Omron CX-Programmer project NewProject (CX-Programmer 9.81)

# PLC NewPLC1: CJ2M CPU11
I/O table (CPU CJ2M-CPU11): rack 0 slot 0 CJ1W-ETN21(ETN21Mode)

## Program NewProgram1 (cyclic task 0)
Local symbols
ETN_CloseRequest 1522.13 BOOL  ; Close Request Switch for ETN Unit
ETN_DataReceived 1516.13 BOOL  ; Data Received Judgment Bit for ETN Unit
ETN_LocalPortNo D30089 UINT  ; Local port number for ETN Unit
ETN_NumberOfSend_ReceiveDataBytes D30093 INT  ; Number of byes of send/receive data for ETN Unit
ETN_NumberOfTCPReceiveDataBytes D30008 UINT  ; Number of byes of TCP receive data for ETN Unit
ETN_OpenRequest 1522.10 BOOL  ; TCP Active Open Request Switch for ETN Unit
ETN_ReceiveRequest 1522.12 BOOL  ; Receive Request Switch for ETN Unit
ETN_RemoteIPAddress_1 D30090 UINT  ; Remote IP address for ETN Unit
ETN_RemoteIPAddress_2 D30091 UINT  ; Remote IP address for ETN Unit
ETN_RemotePortNo D30092 UINT  ; Remote port number for ETN Unit
ETN_ResponseCode D30097 UINT  ; Response code for ETN Unit
ETN_SendRequest 1522.11 BOOL  ; Send Request Switch for ETN Unit
ETN_Send_ReceiveDataAddress_1 D30094 UINT  ; Send/receive data address for ETN Unit
ETN_Send_ReceiveDataAddress_2 D30095 UINT  ; Send/receive data address for ETN Unit
ETN_SocketNo8 D30088 UINT  ; Socket option for ETN Unit/Socket No. 8
ETN_TCPConnectionStatus D30016 UINT  ; TCP connection status for ETN Unit
ETN_TimeoutValue D30096 UINT  ; Timeout value for ETN Unit
Input_CloseMonitorTime_BCD 5013 UINT_BCD  ; Close monitoring time (BCD)
Input_NumberOfSendDataBytes D9000 UINT  ; Number of bytes of send data
Input_OpenMonitorTime_BCD 5010 UINT_BCD  ; Open monitoring time (BCD)
Input_ReceiveMonitorTime_BCD 5012 UINT_BCD  ; Receive monitoring time (BCD)
Input_ReceiveProcessingRequired_NotRequired 5020 UINT  ; Sets whether or not receive processing is required for send processing.
Input_ReceiveStandbyTime_BIN 5014 UINT  ; Receive Standby Time (BIN)
Input_SendData D9001 WORD[128]  ; Send data
Input_SendMonitorTime_BCD 5011 UINT_BCD  ; Send monitoring time (BCD)
Input_Start 5000.00 BOOL  ; Switch to start communications processing (Manually turned ON)
Internal_CloseErrorEnd 5004.02 BOOL  ; Error end ЃЁ End of communications
Internal_CloseExecuting 5004.00 BOOL  ; Keeps ON status until end of close processing.
Internal_CloseMonitorTimerON T1003 BOOL  ; Close processing monitor timer
Internal_CloseNormalEnd 5004.01 BOOL  ; Normal end ЃЁ End of communications
Internal_CloseResponseCodeError 5004.03 BOOL  ; ResponseCodeError
Internal_CloseStatusError 5004.05 BOOL  ; TCP close status error
Internal_CloseTimeout 5004.04 BOOL  ; Timeout
Internal_CommunicationsExecuting 5000.01 BOOL  ; Keeps ON status until end of communications processing. ЃЁ To open processing
Internal_InitialSetupEnd 5000.04 BOOL  ; Ends initial setup. ЃЁ To open processing
Internal_OpenErrorEnd 5001.02 BOOL  ; Error end ЃЁ Close processing
Internal_OpenExecuting 5001.00 BOOL  ; Keeps ON status until end of open processing.
Internal_OpenMonitorTimerON T1000 BOOL  ; Open processing monitor timer
Internal_OpenNormalEnd 5001.01 BOOL  ; Normal end ЃЁ To send processing
Internal_OpenResponseCodeError 5001.03 BOOL  ; ResponseCodeError
Internal_OpenTimeout 5001.04 BOOL  ; Timeout
Internal_ReceiveCodeReaderError 5003.05 BOOL  ; Code reader error
Internal_ReceiveDataAddressType 5110 UINT  ; Receive data address type
Internal_ReceiveDataFirstWord 5111 INT  ; Receive data first word address
Internal_ReceiveDataFirstWordIncrement 5112 INT  ; Receive data first word increment
Internal_ReceiveDataFirstWordIncrementRemaining 5113 INT  ; Receive data first word increment remaining
Internal_ReceiveDataJudgmentArea_UINT 5114 UINT  ; Area used to convert receive data to UINT for judgment
Internal_ReceiveErrorEnd 5003.02 BOOL  ; Error end ЃЁ Close processing
Internal_ReceiveExecuting 5003.00 BOOL  ; Keeps ON status until end of receive processing.
Internal_ReceiveMonitorTimerON T1002 BOOL  ; Receive processing monitor timer
Internal_ReceiveNormalEnd 5003.01 BOOL  ; Normal end ЃЁ To close processing
Internal_ReceiveRepetitionON 5003.06 BOOL  ; Receive request repetition
Internal_ReceiveRequestON 5003.07 BOOL  ; ON-OFF bit for receive request repetition
Internal_ReceiveResponseCodeError 5003.03 BOOL  ; ResponseCodeError
Internal_ReceiveTimeout 5003.04 BOOL  ; Timeout
Internal_SendDataAddressType 5030 UINT  ; Send data address type
Internal_SendDataFirstWord 5031 UINT  ; Send data first word address
Internal_SendErrorEnd 5002.02 BOOL  ; Error end ЃЁ Close processing
Internal_SendExecuting 5002.00 BOOL  ; Keeps ON status until end of send processing.
Internal_SendMonitorTimerON T1001 BOOL  ; Send processing monitor timer
Internal_SendNormalEnd 5002.01 BOOL  ; Normal end ЃЁ To receive processing
Internal_SendResponseCodeError 5002.03 BOOL  ; ResponseCodeError
Internal_SendTimeout 5002.04 BOOL  ; Timeout
Internal_TCPConnectionStatus 5005 UINT  ; TCP connection status judgment area
Internal_TCPReceiveProcessingNotRequired 5000.03 BOOL  ; Executes send processing by skipping receive processing after send processing.
Internal_TCPReceiveProcessingRequired 5000.02 BOOL  ; Executes receive processing after send processing.
Output_CloseErrorCode H404 WORD  ; Close processing response code/timeout code
Output_CodeReaderErrorCode H403 WORD  ; Code reader end code/response code
Output_NumberOfReceiveDataBytes D10000 INT  ; Number of bytes of receive data storage area
Output_OpenErrorCode H400 WORD  ; Open processing response code/timeout code
Output_ReceiveData D10001 WORD[2000]  ; Received data storage area
Output_ReceiveErrorCode H402 WORD  ; Receive processing response code/timeout code
Output_SendErrorCode H401 WORD  ; Send processing response code/timeout code

### Section Start_and_Setup

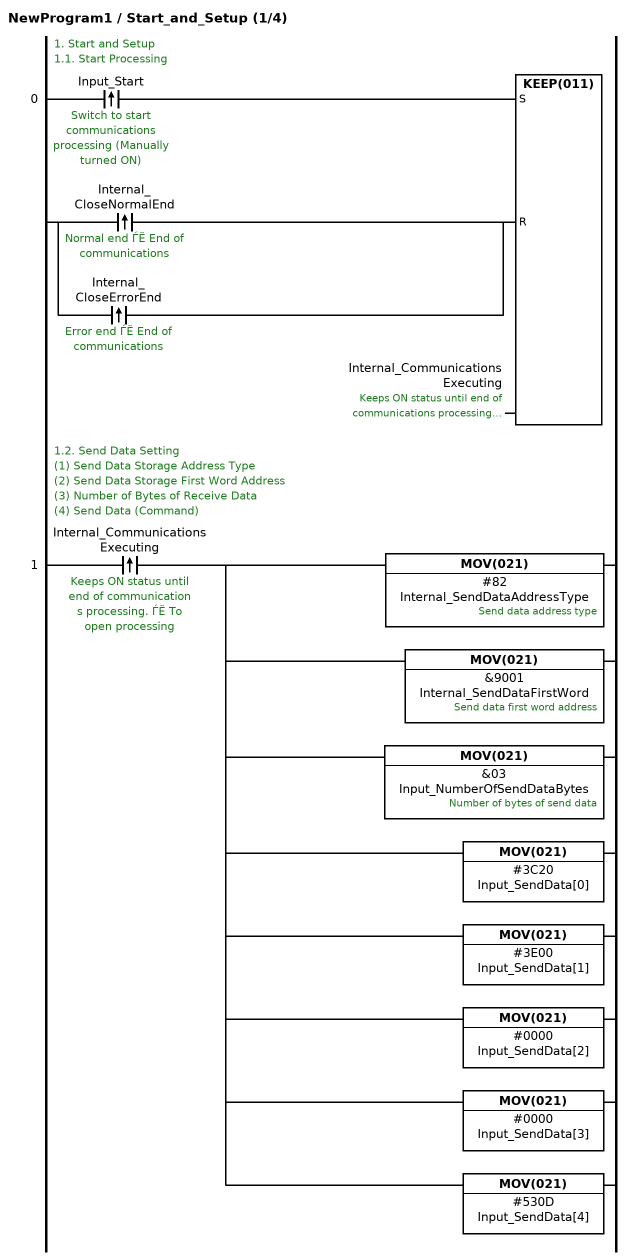
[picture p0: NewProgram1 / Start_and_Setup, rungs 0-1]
; rung 0: 1. Start and Setup / 1.1. Start Processing
@LD Input_Start  ; Switch to start communications processing (Manually turned ON)
@LD Internal_CloseNormalEnd  ; Normal end ЃЁ End of communications
@OR Internal_CloseErrorEnd  ; Error end ЃЁ End of communications
KEEP(011) Internal_CommunicationsExecuting  ; Keeps ON status until end of communications processing. ЃЁ To open processing
; rung 1: 1.2. Send Data Setting / (1) Send Data Storage Address Type / (2) Send Data Storage First Word Address / (3) Number of Bytes of Receive Data / (4) Send Data (Command)
@LD Internal_CommunicationsExecuting  ; Keeps ON status until end of communications processing. ЃЁ To open processing
MOV(021) #82 Internal_SendDataAddressType  ; Send data address type
MOV(021) &9001 Internal_SendDataFirstWord  ; Send data first word address
MOV(021) &03 Input_NumberOfSendDataBytes  ; Number of bytes of send data
MOV(021) #3C20 Input_SendData[0]
MOV(021) #3E00 Input_SendData[1]
MOV(021) #0000 Input_SendData[2]
MOV(021) #0000 Input_SendData[3]
MOV(021) #530D Input_SendData[4]

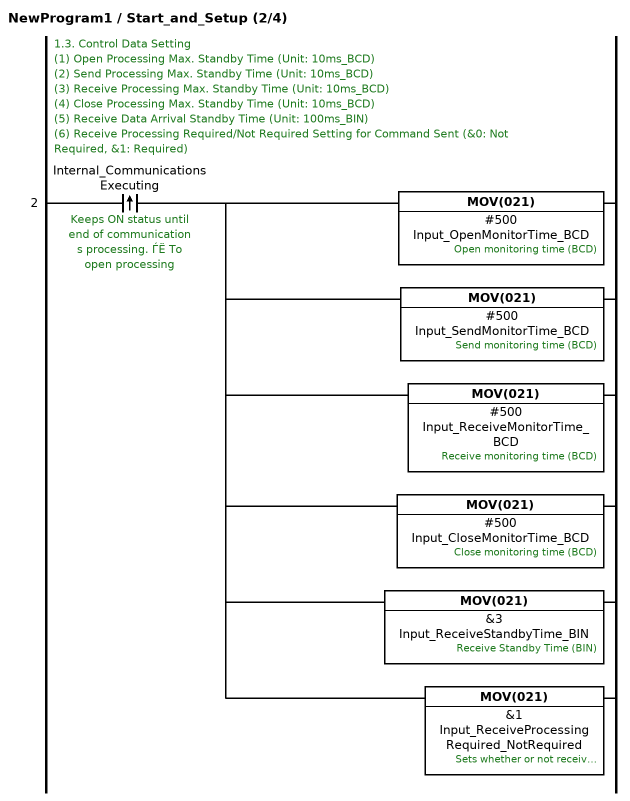
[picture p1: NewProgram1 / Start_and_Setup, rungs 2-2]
; rung 2: 1.3. Control Data Setting / (1) Open Processing Max. Standby Time (Unit: 10ms_BCD) / (2) Send Processing Max. Standby Time (Unit: 10ms_BCD) / (3) Receive Processing Max. Standby Time (Unit: 10ms_BCD) / (4) Close Processing Max. Standby Time (Unit: 10ms_BCD) / (5) Receive Data Arrival Standby Time (Unit: 100ms_BIN) / (6) Receive Processing Required/Not Required Setting for Command Sent (&0: Not Required, &1: Required)
@LD Internal_CommunicationsExecuting  ; Keeps ON status until end of communications processing. ЃЁ To open processing
MOV(021) #500 Input_OpenMonitorTime_BCD  ; Open monitoring time (BCD)
MOV(021) #500 Input_SendMonitorTime_BCD  ; Send monitoring time (BCD)
MOV(021) #500 Input_ReceiveMonitorTime_BCD  ; Receive monitoring time (BCD)
MOV(021) #500 Input_CloseMonitorTime_BCD  ; Close monitoring time (BCD)
MOV(021) &3 Input_ReceiveStandbyTime_BIN  ; Receive Standby Time (BIN)
MOV(021) &1 Input_ReceiveProcessingRequired_NotRequired  ; Sets whether or not receive processing is required for send processing.

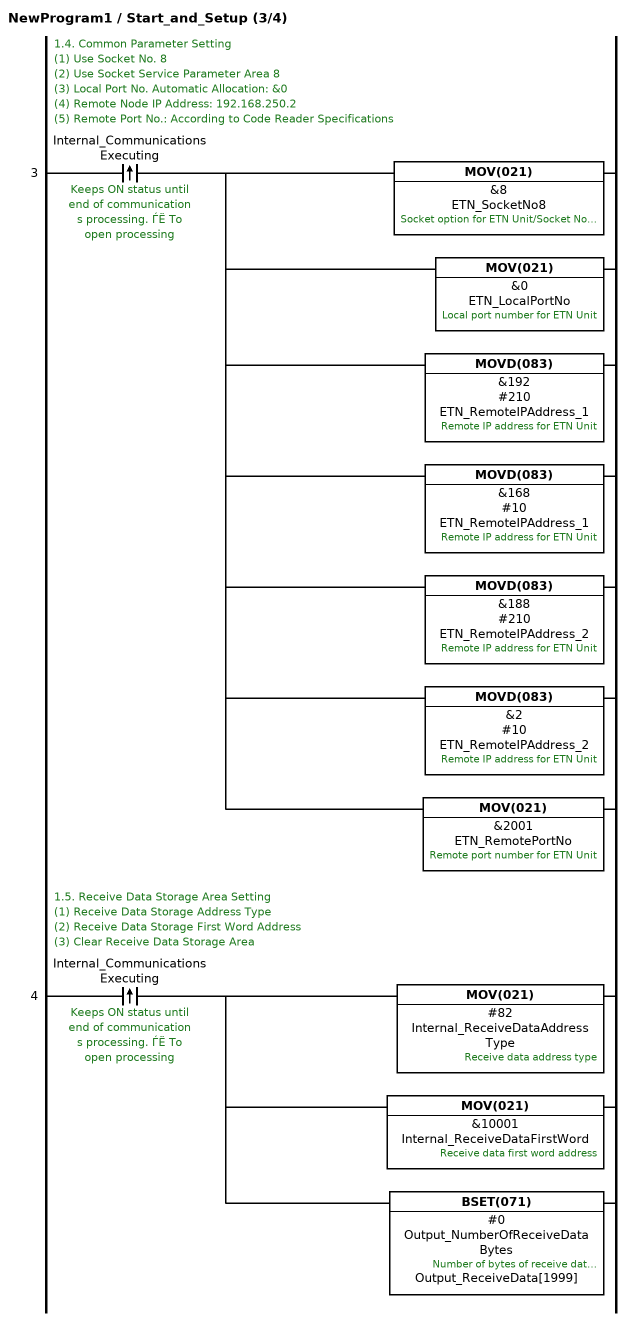
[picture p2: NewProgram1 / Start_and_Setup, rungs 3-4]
; rung 3: 1.4. Common Parameter Setting / (1) Use Socket No. 8 / (2) Use Socket Service Parameter Area 8 / (3) Local Port No. Automatic Allocation: &0 / (4) Remote Node IP Address: 192.168.250.2 / (5) Remote Port No.: According to Code Reader Specifications
@LD Internal_CommunicationsExecuting  ; Keeps ON status until end of communications processing. ЃЁ To open processing
MOV(021) &8 ETN_SocketNo8  ; Socket option for ETN Unit/Socket No. 8
MOV(021) &0 ETN_LocalPortNo  ; Local port number for ETN Unit
MOVD(083) &192 #210 ETN_RemoteIPAddress_1  ; Remote IP address for ETN Unit
MOVD(083) &168 #10 ETN_RemoteIPAddress_1  ; Remote IP address for ETN Unit
MOVD(083) &188 #210 ETN_RemoteIPAddress_2  ; Remote IP address for ETN Unit
MOVD(083) &2 #10 ETN_RemoteIPAddress_2  ; Remote IP address for ETN Unit
MOV(021) &2001 ETN_RemotePortNo  ; Remote port number for ETN Unit
; rung 4: 1.5. Receive Data Storage Area Setting / (1) Receive Data Storage Address Type / (2) Receive Data Storage First Word Address / (3) Clear Receive Data Storage Area
@LD Internal_CommunicationsExecuting  ; Keeps ON status until end of communications processing. ЃЁ To open processing
MOV(021) #82 Internal_ReceiveDataAddressType  ; Receive data address type
MOV(021) &10001 Internal_ReceiveDataFirstWord  ; Receive data first word address
BSET(071) #0 Output_NumberOfReceiveDataBytes Output_ReceiveData[1999]  ; Number of bytes of receive data storage area

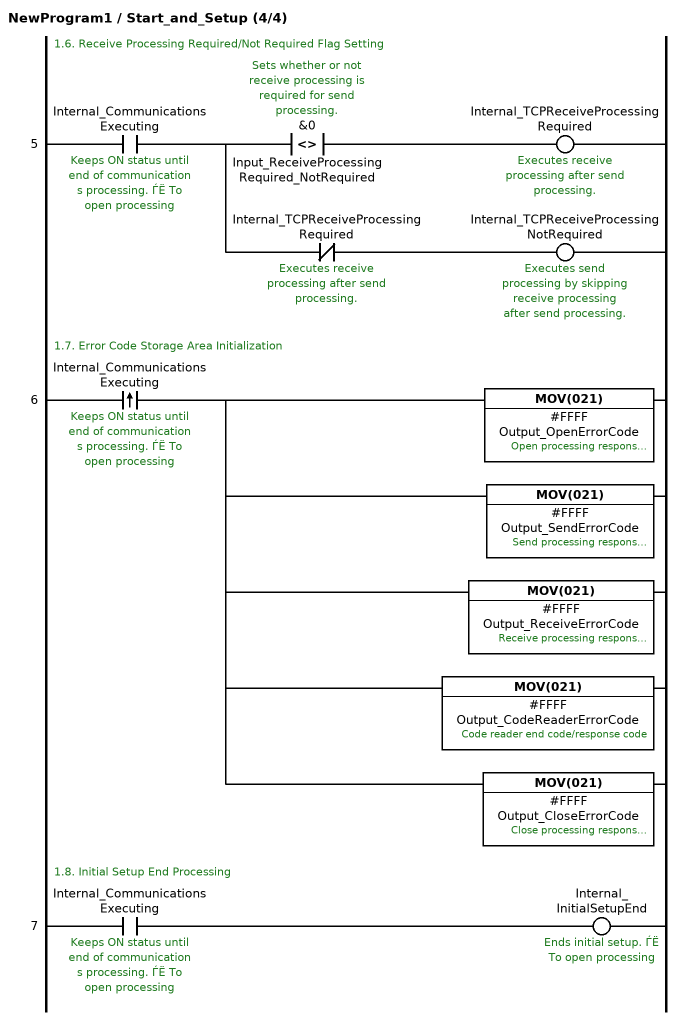
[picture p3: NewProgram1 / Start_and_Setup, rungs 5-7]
; rung 5: 1.6. Receive Processing Required/Not Required Flag Setting
LD Internal_CommunicationsExecuting  ; Keeps ON status until end of communications processing. ЃЁ To open processing
OUT TR0
AND<>(305) &0 Input_ReceiveProcessingRequired_NotRequired  ; Sets whether or not receive processing is required for send processing.
OUT Internal_TCPReceiveProcessingRequired  ; Executes receive processing after send processing.
LD TR0
ANDNOT Internal_TCPReceiveProcessingRequired  ; Executes receive processing after send processing.
OUT Internal_TCPReceiveProcessingNotRequired  ; Executes send processing by skipping receive processing after send processing.
; rung 6: 1.7. Error Code Storage Area Initialization
@LD Internal_CommunicationsExecuting  ; Keeps ON status until end of communications processing. ЃЁ To open processing
MOV(021) #FFFF Output_OpenErrorCode  ; Open processing response code/timeout code
MOV(021) #FFFF Output_SendErrorCode  ; Send processing response code/timeout code
MOV(021) #FFFF Output_ReceiveErrorCode  ; Receive processing response code/timeout code
MOV(021) #FFFF Output_CodeReaderErrorCode  ; Code reader end code/response code
MOV(021) #FFFF Output_CloseErrorCode  ; Close processing response code/timeout code
; rung 7: 1.8. Initial Setup End Processing
LD Internal_CommunicationsExecuting  ; Keeps ON status until end of communications processing. ЃЁ To open processing
OUT Internal_InitialSetupEnd  ; Ends initial setup. ЃЁ To open processing

### Section Open_Processing

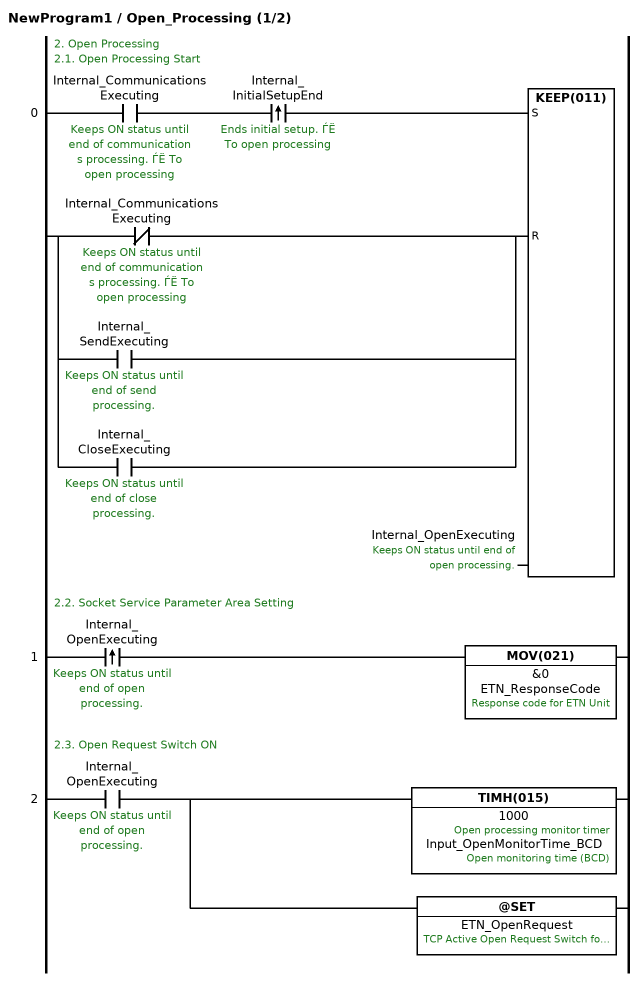
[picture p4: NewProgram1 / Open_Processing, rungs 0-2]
; rung 0: 2. Open Processing / 2.1. Open Processing Start
LD Internal_CommunicationsExecuting  ; Keeps ON status until end of communications processing. ЃЁ To open processing
@AND Internal_InitialSetupEnd  ; Ends initial setup. ЃЁ To open processing
LDNOT Internal_CommunicationsExecuting  ; Keeps ON status until end of communications processing. ЃЁ To open processing
OR Internal_SendExecuting  ; Keeps ON status until end of send processing.
OR Internal_CloseExecuting  ; Keeps ON status until end of close processing.
KEEP(011) Internal_OpenExecuting  ; Keeps ON status until end of open processing.
; rung 1: 2.2. Socket Service Parameter Area Setting
@LD Internal_OpenExecuting  ; Keeps ON status until end of open processing.
MOV(021) &0 ETN_ResponseCode  ; Response code for ETN Unit
; rung 2: 2.3. Open Request Switch ON
LD Internal_OpenExecuting  ; Keeps ON status until end of open processing.
TIMH(015) 1000 Input_OpenMonitorTime_BCD  ; Open monitoring time (BCD), Open processing monitor timer
@SET ETN_OpenRequest  ; TCP Active Open Request Switch for ETN Unit

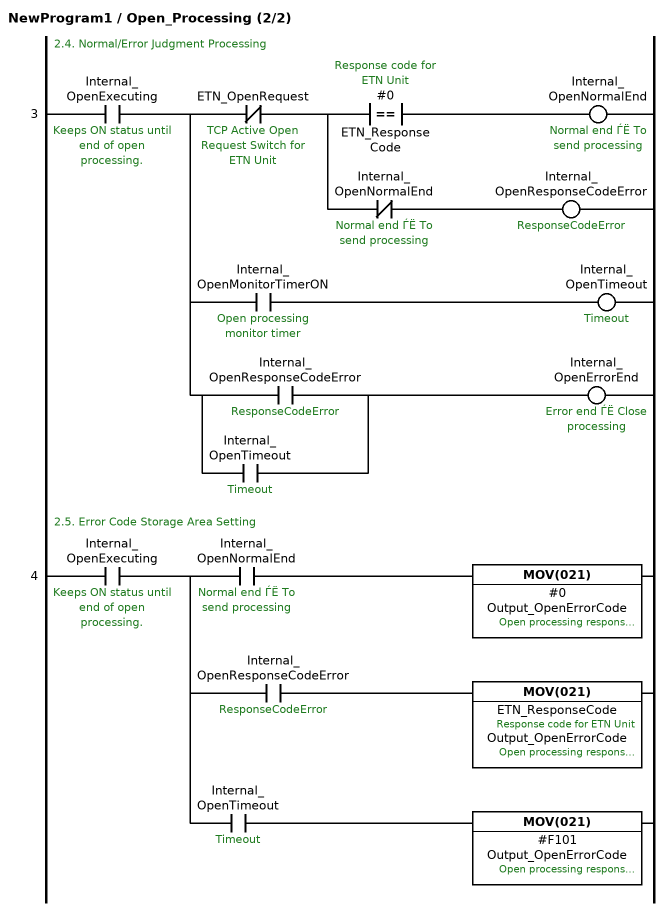
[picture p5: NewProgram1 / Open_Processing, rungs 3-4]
; rung 3: 2.4. Normal/Error Judgment Processing
LD Internal_OpenExecuting  ; Keeps ON status until end of open processing.
OUT TR0
ANDNOT ETN_OpenRequest  ; TCP Active Open Request Switch for ETN Unit
OUT TR1
AND=(300) #0 ETN_ResponseCode  ; Response code for ETN Unit
OUT Internal_OpenNormalEnd  ; Normal end ЃЁ To send processing
LD TR1
ANDNOT Internal_OpenNormalEnd  ; Normal end ЃЁ To send processing
OUT Internal_OpenResponseCodeError  ; ResponseCodeError
LD TR0
AND Internal_OpenMonitorTimerON  ; Open processing monitor timer
OUT Internal_OpenTimeout  ; Timeout
LD TR0
LD Internal_OpenResponseCodeError  ; ResponseCodeError
OR Internal_OpenTimeout  ; Timeout
ANDLD
OUT Internal_OpenErrorEnd  ; Error end ЃЁ Close processing
; rung 4: 2.5. Error Code Storage Area Setting
LD Internal_OpenExecuting  ; Keeps ON status until end of open processing.
OUT TR0
AND Internal_OpenNormalEnd  ; Normal end ЃЁ To send processing
MOV(021) #0 Output_OpenErrorCode  ; Open processing response code/timeout code
LD TR0
AND Internal_OpenResponseCodeError  ; ResponseCodeError
MOV(021) ETN_ResponseCode Output_OpenErrorCode  ; Response code for ETN Unit, Open processing response code/timeout code
LD TR0
AND Internal_OpenTimeout  ; Timeout
MOV(021) #F101 Output_OpenErrorCode  ; Open processing response code/timeout code

### Section Send_Processing

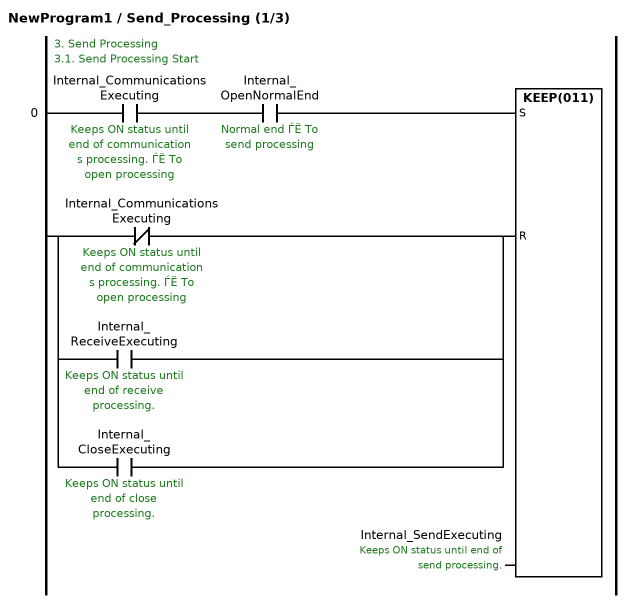
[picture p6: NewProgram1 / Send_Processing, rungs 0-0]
; rung 0: 3. Send Processing / 3.1. Send Processing Start
LD Internal_CommunicationsExecuting  ; Keeps ON status until end of communications processing. ЃЁ To open processing
AND Internal_OpenNormalEnd  ; Normal end ЃЁ To send processing
LDNOT Internal_CommunicationsExecuting  ; Keeps ON status until end of communications processing. ЃЁ To open processing
OR Internal_ReceiveExecuting  ; Keeps ON status until end of receive processing.
OR Internal_CloseExecuting  ; Keeps ON status until end of close processing.
KEEP(011) Internal_SendExecuting  ; Keeps ON status until end of send processing.

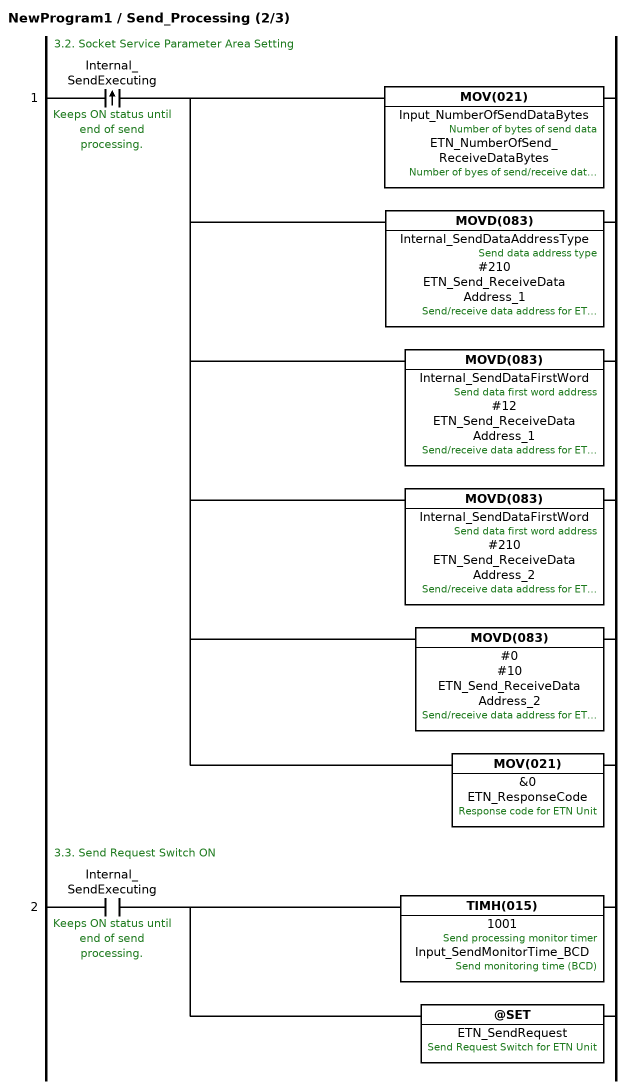
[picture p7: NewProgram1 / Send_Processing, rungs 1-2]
; rung 1: 3.2. Socket Service Parameter Area Setting
@LD Internal_SendExecuting  ; Keeps ON status until end of send processing.
MOV(021) Input_NumberOfSendDataBytes ETN_NumberOfSend_ReceiveDataBytes  ; Number of bytes of send data, Number of byes of send/receive data for ETN Unit
MOVD(083) Internal_SendDataAddressType #210 ETN_Send_ReceiveDataAddress_1  ; Send data address type, Send/receive data address for ETN Unit
MOVD(083) Internal_SendDataFirstWord #12 ETN_Send_ReceiveDataAddress_1  ; Send data first word address, Send/receive data address for ETN Unit
MOVD(083) Internal_SendDataFirstWord #210 ETN_Send_ReceiveDataAddress_2  ; Send data first word address, Send/receive data address for ETN Unit
MOVD(083) #0 #10 ETN_Send_ReceiveDataAddress_2  ; Send/receive data address for ETN Unit
MOV(021) &0 ETN_ResponseCode  ; Response code for ETN Unit
; rung 2: 3.3. Send Request Switch ON
LD Internal_SendExecuting  ; Keeps ON status until end of send processing.
TIMH(015) 1001 Input_SendMonitorTime_BCD  ; Send monitoring time (BCD), Send processing monitor timer
@SET ETN_SendRequest  ; Send Request Switch for ETN Unit

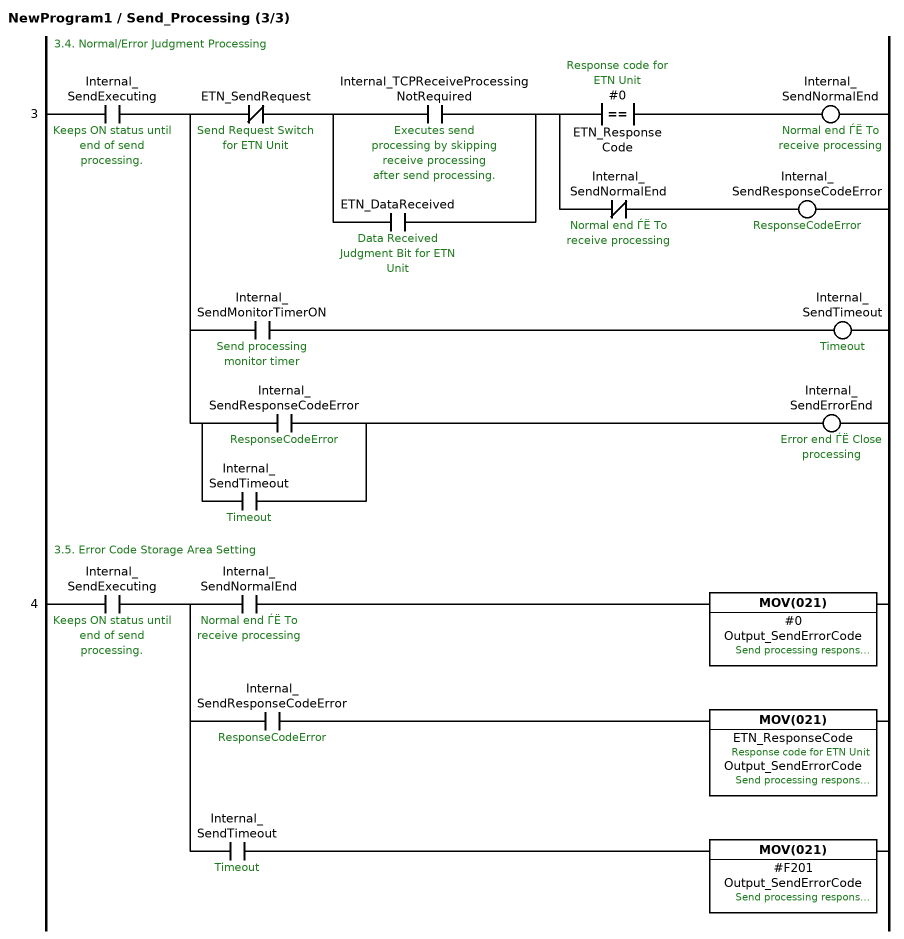
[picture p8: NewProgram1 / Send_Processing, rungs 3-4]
; rung 3: 3.4. Normal/Error Judgment Processing
LD Internal_SendExecuting  ; Keeps ON status until end of send processing.
OUT TR0
ANDNOT ETN_SendRequest  ; Send Request Switch for ETN Unit
LD Internal_TCPReceiveProcessingNotRequired  ; Executes send processing by skipping receive processing after send processing.
OR ETN_DataReceived  ; Data Received Judgment Bit for ETN Unit
ANDLD
OUT TR1
AND=(300) #0 ETN_ResponseCode  ; Response code for ETN Unit
OUT Internal_SendNormalEnd  ; Normal end ЃЁ To receive processing
LD TR1
ANDNOT Internal_SendNormalEnd  ; Normal end ЃЁ To receive processing
OUT Internal_SendResponseCodeError  ; ResponseCodeError
LD TR0
AND Internal_SendMonitorTimerON  ; Send processing monitor timer
OUT Internal_SendTimeout  ; Timeout
LD TR0
LD Internal_SendResponseCodeError  ; ResponseCodeError
OR Internal_SendTimeout  ; Timeout
ANDLD
OUT Internal_SendErrorEnd  ; Error end ЃЁ Close processing
; rung 4: 3.5. Error Code Storage Area Setting
LD Internal_SendExecuting  ; Keeps ON status until end of send processing.
OUT TR0
AND Internal_SendNormalEnd  ; Normal end ЃЁ To receive processing
MOV(021) #0 Output_SendErrorCode  ; Send processing response code/timeout code
LD TR0
AND Internal_SendResponseCodeError  ; ResponseCodeError
MOV(021) ETN_ResponseCode Output_SendErrorCode  ; Response code for ETN Unit, Send processing response code/timeout code
LD TR0
AND Internal_SendTimeout  ; Timeout
MOV(021) #F201 Output_SendErrorCode  ; Send processing response code/timeout code

### Section Receive_Processing

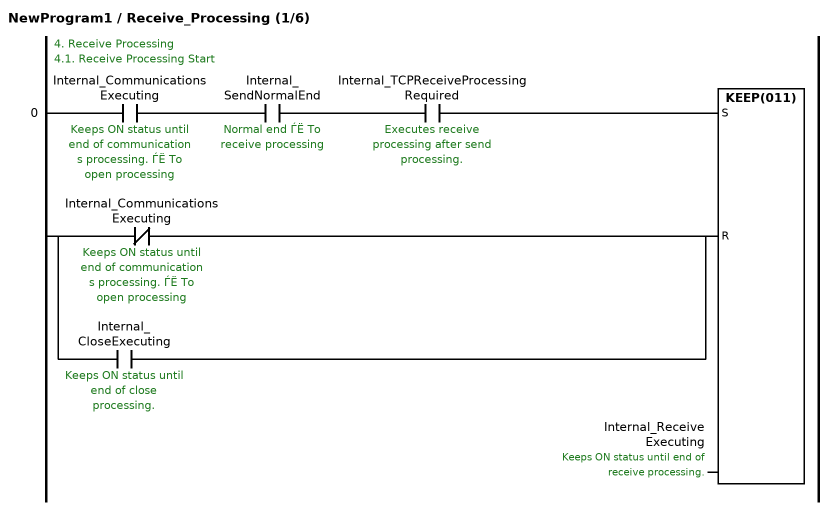
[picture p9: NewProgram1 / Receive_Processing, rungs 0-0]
; rung 0: 4. Receive Processing / 4.1. Receive Processing Start
LD Internal_CommunicationsExecuting  ; Keeps ON status until end of communications processing. ЃЁ To open processing
AND Internal_SendNormalEnd  ; Normal end ЃЁ To receive processing
AND Internal_TCPReceiveProcessingRequired  ; Executes receive processing after send processing.
LDNOT Internal_CommunicationsExecuting  ; Keeps ON status until end of communications processing. ЃЁ To open processing
OR Internal_CloseExecuting  ; Keeps ON status until end of close processing.
KEEP(011) Internal_ReceiveExecuting  ; Keeps ON status until end of receive processing.

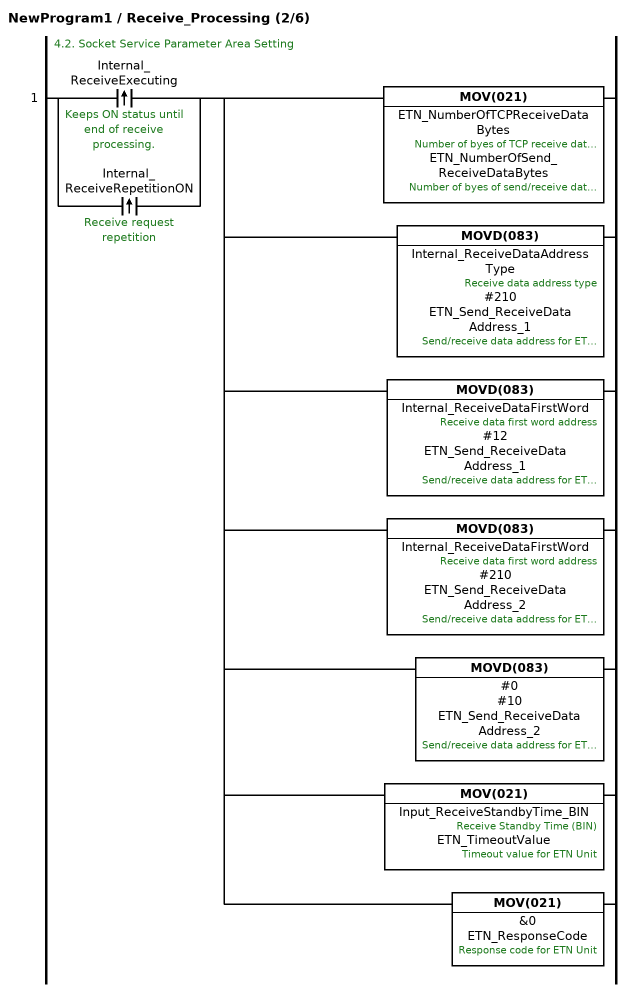
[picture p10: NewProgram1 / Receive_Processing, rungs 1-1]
; rung 1: 4.2. Socket Service Parameter Area Setting
@LD Internal_ReceiveExecuting  ; Keeps ON status until end of receive processing.
@OR Internal_ReceiveRepetitionON  ; Receive request repetition
MOV(021) ETN_NumberOfTCPReceiveDataBytes ETN_NumberOfSend_ReceiveDataBytes  ; Number of byes of TCP receive data for ETN Unit, Number of byes of send/receive data for ETN Unit
MOVD(083) Internal_ReceiveDataAddressType #210 ETN_Send_ReceiveDataAddress_1  ; Receive data address type, Send/receive data address for ETN Unit
MOVD(083) Internal_ReceiveDataFirstWord #12 ETN_Send_ReceiveDataAddress_1  ; Receive data first word address, Send/receive data address for ETN Unit
MOVD(083) Internal_ReceiveDataFirstWord #210 ETN_Send_ReceiveDataAddress_2  ; Receive data first word address, Send/receive data address for ETN Unit
MOVD(083) #0 #10 ETN_Send_ReceiveDataAddress_2  ; Send/receive data address for ETN Unit
MOV(021) Input_ReceiveStandbyTime_BIN ETN_TimeoutValue  ; Receive Standby Time (BIN), Timeout value for ETN Unit
MOV(021) &0 ETN_ResponseCode  ; Response code for ETN Unit

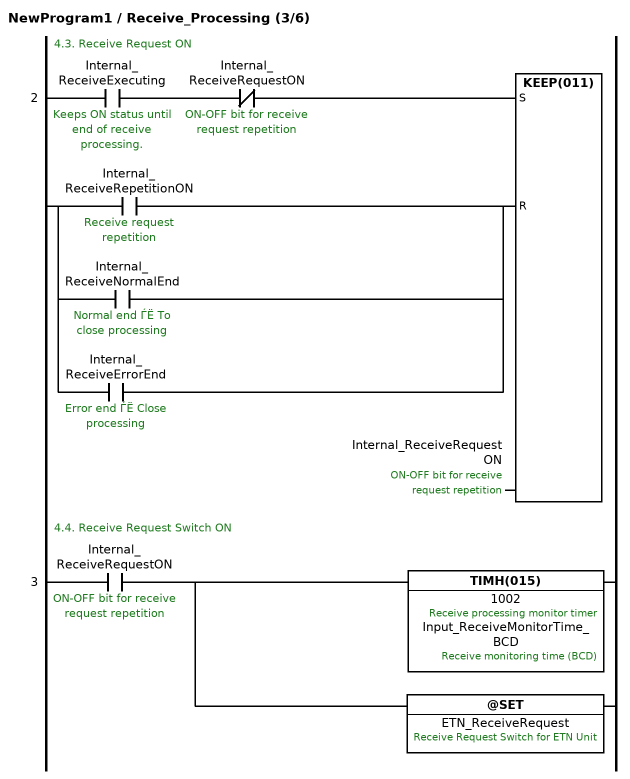
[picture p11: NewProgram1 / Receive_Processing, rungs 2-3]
; rung 2: 4.3. Receive Request ON
LD Internal_ReceiveExecuting  ; Keeps ON status until end of receive processing.
ANDNOT Internal_ReceiveRequestON  ; ON-OFF bit for receive request repetition
LD Internal_ReceiveRepetitionON  ; Receive request repetition
OR Internal_ReceiveNormalEnd  ; Normal end ЃЁ To close processing
OR Internal_ReceiveErrorEnd  ; Error end ЃЁ Close processing
KEEP(011) Internal_ReceiveRequestON  ; ON-OFF bit for receive request repetition
; rung 3: 4.4. Receive Request Switch ON
LD Internal_ReceiveRequestON  ; ON-OFF bit for receive request repetition
TIMH(015) 1002 Input_ReceiveMonitorTime_BCD  ; Receive monitoring time (BCD), Receive processing monitor timer
@SET ETN_ReceiveRequest  ; Receive Request Switch for ETN Unit

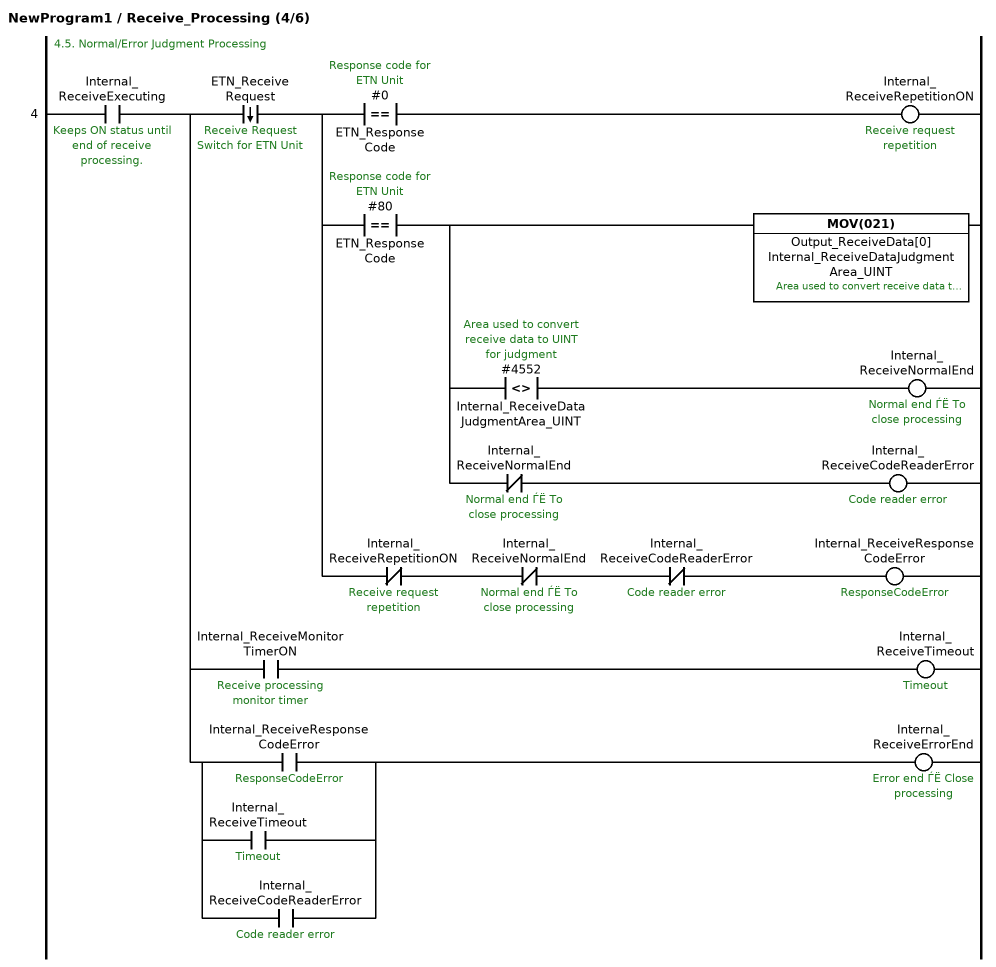
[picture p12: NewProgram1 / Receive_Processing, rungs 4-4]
; rung 4: 4.5. Normal/Error Judgment Processing
LD Internal_ReceiveExecuting  ; Keeps ON status until end of receive processing.
OUT TR0
%AND ETN_ReceiveRequest  ; Receive Request Switch for ETN Unit
OUT TR1
AND=(300) #0 ETN_ResponseCode  ; Response code for ETN Unit
OUT Internal_ReceiveRepetitionON  ; Receive request repetition
LD TR1
AND=(300) #80 ETN_ResponseCode  ; Response code for ETN Unit
OUT TR2
MOV(021) Output_ReceiveData[0] Internal_ReceiveDataJudgmentArea_UINT  ; Area used to convert receive data to UINT for judgment
AND<>(305) #4552 Internal_ReceiveDataJudgmentArea_UINT  ; Area used to convert receive data to UINT for judgment
OUT Internal_ReceiveNormalEnd  ; Normal end ЃЁ To close processing
LD TR2
ANDNOT Internal_ReceiveNormalEnd  ; Normal end ЃЁ To close processing
OUT Internal_ReceiveCodeReaderError  ; Code reader error
LD TR1
ANDNOT Internal_ReceiveRepetitionON  ; Receive request repetition
ANDNOT Internal_ReceiveNormalEnd  ; Normal end ЃЁ To close processing
ANDNOT Internal_ReceiveCodeReaderError  ; Code reader error
OUT Internal_ReceiveResponseCodeError  ; ResponseCodeError
LD TR0
AND Internal_ReceiveMonitorTimerON  ; Receive processing monitor timer
OUT Internal_ReceiveTimeout  ; Timeout
LD TR0
LD Internal_ReceiveResponseCodeError  ; ResponseCodeError
OR Internal_ReceiveTimeout  ; Timeout
OR Internal_ReceiveCodeReaderError  ; Code reader error
ANDLD
OUT Internal_ReceiveErrorEnd  ; Error end ЃЁ Close processing

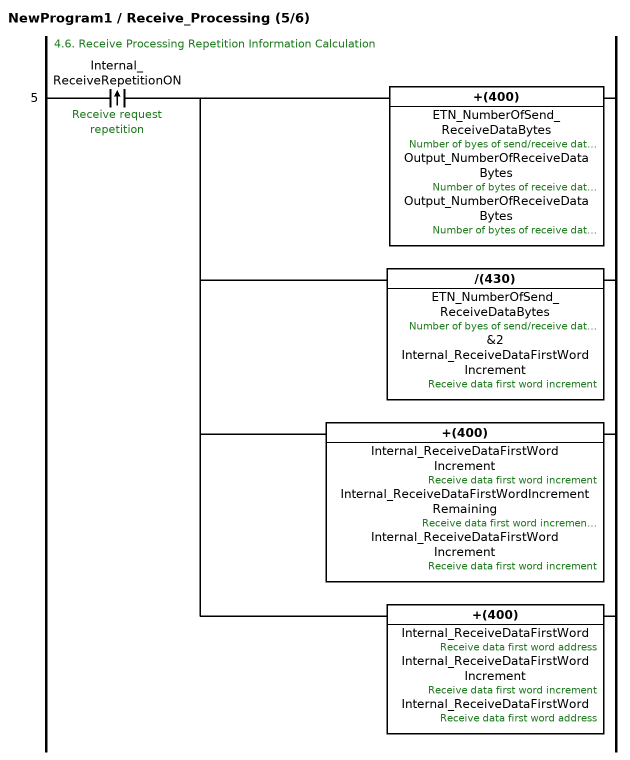
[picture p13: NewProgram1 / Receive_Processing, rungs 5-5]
; rung 5: 4.6. Receive Processing Repetition Information Calculation
@LD Internal_ReceiveRepetitionON  ; Receive request repetition
+(400) ETN_NumberOfSend_ReceiveDataBytes Output_NumberOfReceiveDataBytes Output_NumberOfReceiveDataBytes  ; Number of byes of send/receive data for ETN Unit, Number of bytes of receive data storage area
/(430) ETN_NumberOfSend_ReceiveDataBytes &2 Internal_ReceiveDataFirstWordIncrement  ; Number of byes of send/receive data for ETN Unit, Receive data first word increment
+(400) Internal_ReceiveDataFirstWordIncrement Internal_ReceiveDataFirstWordIncrementRemaining Internal_ReceiveDataFirstWordIncrement  ; Receive data first word increment, Receive data first word increment remaining
+(400) Internal_ReceiveDataFirstWord Internal_ReceiveDataFirstWordIncrement Internal_ReceiveDataFirstWord  ; Receive data first word address, Receive data first word increment

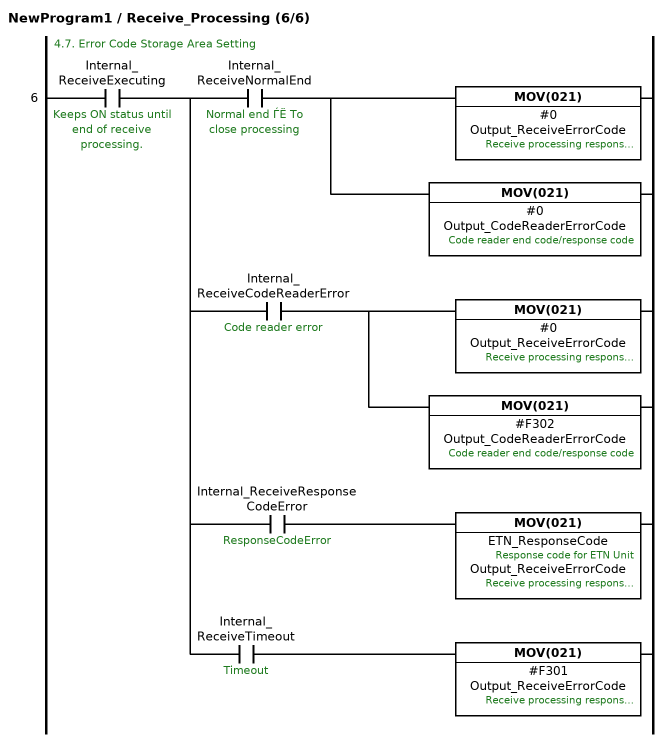
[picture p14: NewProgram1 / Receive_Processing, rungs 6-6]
; rung 6: 4.7. Error Code Storage Area Setting
LD Internal_ReceiveExecuting  ; Keeps ON status until end of receive processing.
OUT TR0
AND Internal_ReceiveNormalEnd  ; Normal end ЃЁ To close processing
MOV(021) #0 Output_ReceiveErrorCode  ; Receive processing response code/timeout code
MOV(021) #0 Output_CodeReaderErrorCode  ; Code reader end code/response code
LD TR0
AND Internal_ReceiveCodeReaderError  ; Code reader error
MOV(021) #0 Output_ReceiveErrorCode  ; Receive processing response code/timeout code
MOV(021) #F302 Output_CodeReaderErrorCode  ; Code reader end code/response code
LD TR0
AND Internal_ReceiveResponseCodeError  ; ResponseCodeError
MOV(021) ETN_ResponseCode Output_ReceiveErrorCode  ; Response code for ETN Unit, Receive processing response code/timeout code
LD TR0
AND Internal_ReceiveTimeout  ; Timeout
MOV(021) #F301 Output_ReceiveErrorCode  ; Receive processing response code/timeout code

### Section Close_Processing

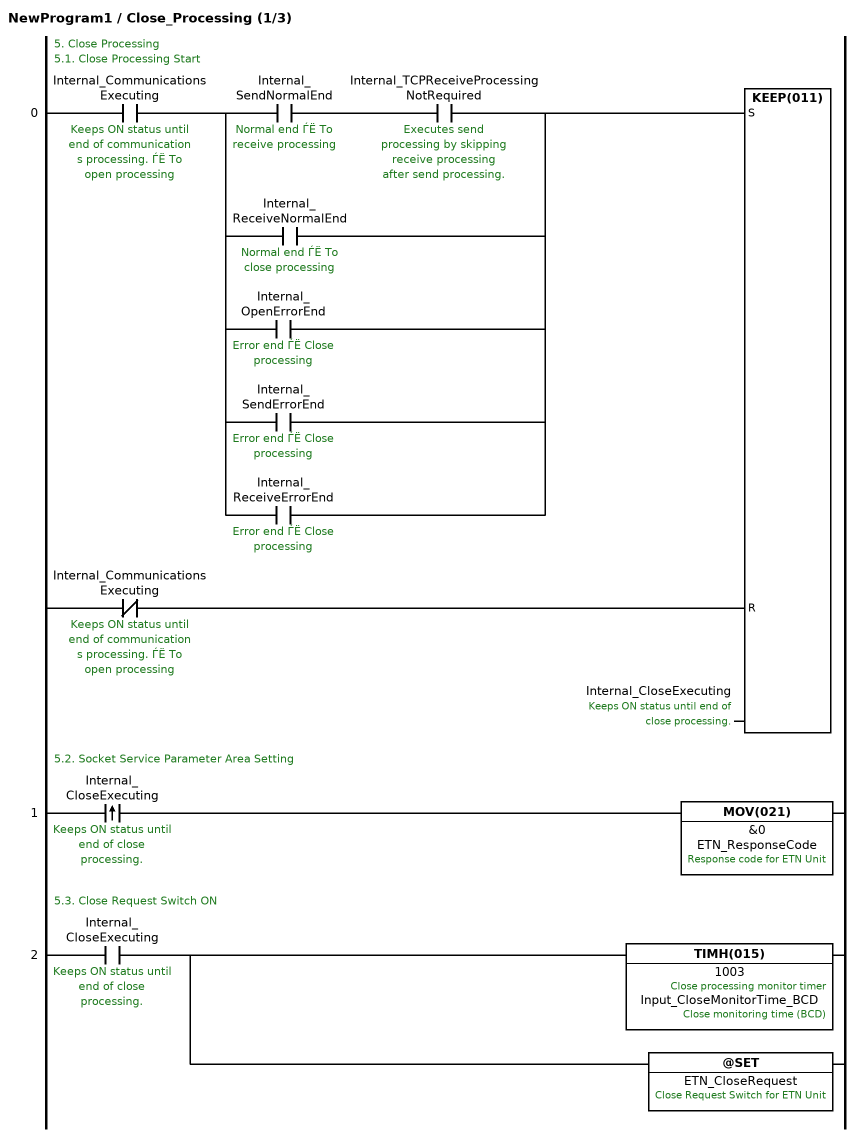
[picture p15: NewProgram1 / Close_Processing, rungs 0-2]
; rung 0: 5. Close Processing / 5.1. Close Processing Start
LD Internal_CommunicationsExecuting  ; Keeps ON status until end of communications processing. ЃЁ To open processing
LD Internal_SendNormalEnd  ; Normal end ЃЁ To receive processing
AND Internal_TCPReceiveProcessingNotRequired  ; Executes send processing by skipping receive processing after send processing.
OR Internal_ReceiveNormalEnd  ; Normal end ЃЁ To close processing
OR Internal_OpenErrorEnd  ; Error end ЃЁ Close processing
OR Internal_SendErrorEnd  ; Error end ЃЁ Close processing
OR Internal_ReceiveErrorEnd  ; Error end ЃЁ Close processing
ANDLD
LDNOT Internal_CommunicationsExecuting  ; Keeps ON status until end of communications processing. ЃЁ To open processing
KEEP(011) Internal_CloseExecuting  ; Keeps ON status until end of close processing.
; rung 1: 5.2. Socket Service Parameter Area Setting
@LD Internal_CloseExecuting  ; Keeps ON status until end of close processing.
MOV(021) &0 ETN_ResponseCode  ; Response code for ETN Unit
; rung 2: 5.3. Close Request Switch ON
LD Internal_CloseExecuting  ; Keeps ON status until end of close processing.
TIMH(015) 1003 Input_CloseMonitorTime_BCD  ; Close monitoring time (BCD), Close processing monitor timer
@SET ETN_CloseRequest  ; Close Request Switch for ETN Unit

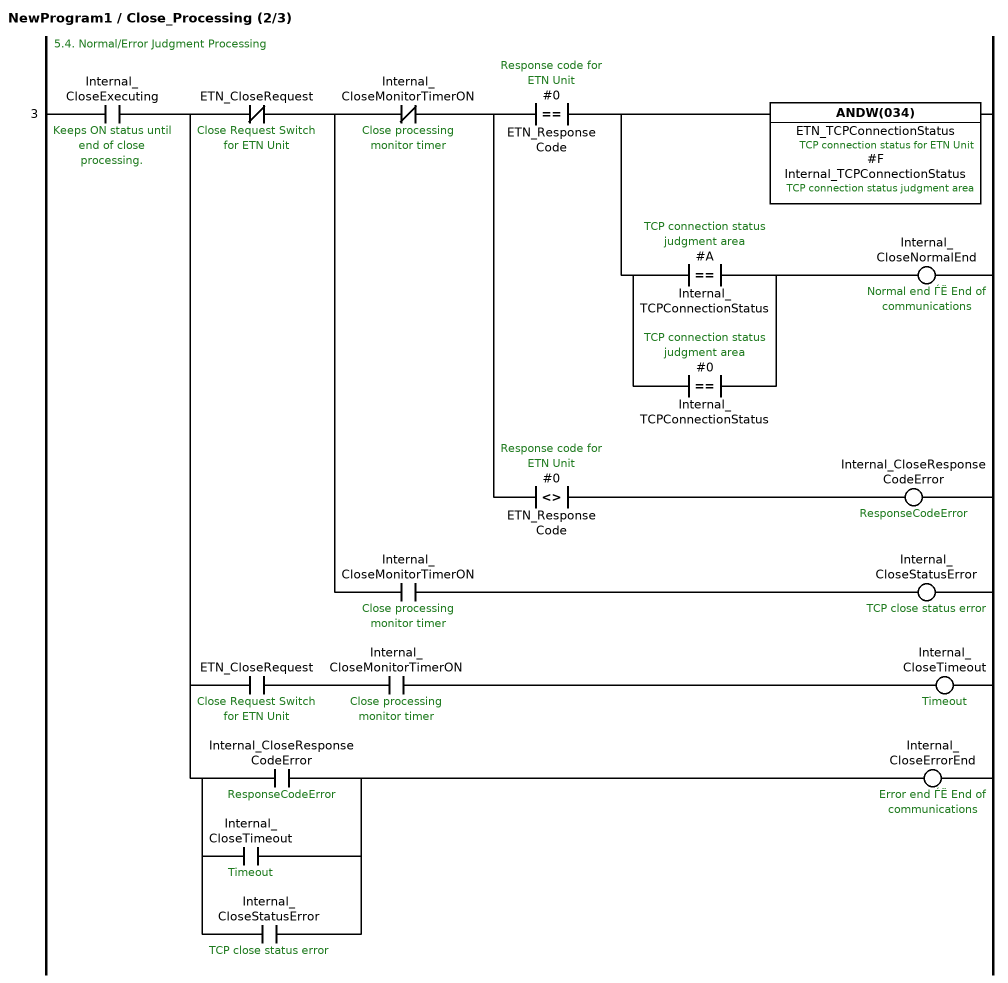
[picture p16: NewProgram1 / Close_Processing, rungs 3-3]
; rung 3: 5.4. Normal/Error Judgment Processing
LD Internal_CloseExecuting  ; Keeps ON status until end of close processing.
OUT TR0
ANDNOT ETN_CloseRequest  ; Close Request Switch for ETN Unit
OUT TR1
ANDNOT Internal_CloseMonitorTimerON  ; Close processing monitor timer
OUT TR2
AND=(300) #0 ETN_ResponseCode  ; Response code for ETN Unit
ANDW(034) ETN_TCPConnectionStatus #F Internal_TCPConnectionStatus  ; TCP connection status for ETN Unit, TCP connection status judgment area
LD=(300) #A Internal_TCPConnectionStatus  ; TCP connection status judgment area
OR=(300) #0 Internal_TCPConnectionStatus  ; TCP connection status judgment area
ANDLD
OUT Internal_CloseNormalEnd  ; Normal end ЃЁ End of communications
LD TR2
AND<>(305) #0 ETN_ResponseCode  ; Response code for ETN Unit
OUT Internal_CloseResponseCodeError  ; ResponseCodeError
LD TR1
AND Internal_CloseMonitorTimerON  ; Close processing monitor timer
OUT Internal_CloseStatusError  ; TCP close status error
LD TR0
AND ETN_CloseRequest  ; Close Request Switch for ETN Unit
AND Internal_CloseMonitorTimerON  ; Close processing monitor timer
OUT Internal_CloseTimeout  ; Timeout
LD TR0
LD Internal_CloseResponseCodeError  ; ResponseCodeError
OR Internal_CloseTimeout  ; Timeout
OR Internal_CloseStatusError  ; TCP close status error
ANDLD
OUT Internal_CloseErrorEnd  ; Error end ЃЁ End of communications

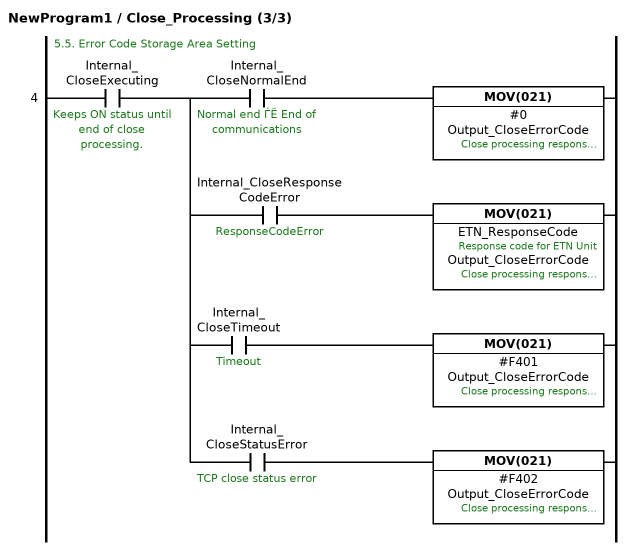
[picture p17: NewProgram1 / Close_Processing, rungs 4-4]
; rung 4: 5.5. Error Code Storage Area Setting
LD Internal_CloseExecuting  ; Keeps ON status until end of close processing.
OUT TR0
AND Internal_CloseNormalEnd  ; Normal end ЃЁ End of communications
MOV(021) #0 Output_CloseErrorCode  ; Close processing response code/timeout code
LD TR0
AND Internal_CloseResponseCodeError  ; ResponseCodeError
MOV(021) ETN_ResponseCode Output_CloseErrorCode  ; Response code for ETN Unit, Close processing response code/timeout code
LD TR0
AND Internal_CloseTimeout  ; Timeout
MOV(021) #F401 Output_CloseErrorCode  ; Close processing response code/timeout code
LD TR0
AND Internal_CloseStatusError  ; TCP close status error
MOV(021) #F402 Output_CloseErrorCode  ; Close processing response code/timeout code

### Section END
; rung 0
END(001)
